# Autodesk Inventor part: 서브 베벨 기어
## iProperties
Created: 2014-10
Part Number: 서브 베벨 기어
Material: Steel, Mild
Document SubType Name: Modeling
Designer: KYOUNG IL JANG
Categories: <?xml version="1.0" encoding="UTF-16"?> <MemberInstance><Categories><FamilyTemplate><FamilyTemplateParameter ValueType="xs:double" Id="1" ObjectReferenceKey="da
Mass: 134.866 g
Surface Area: 63.6518 cm^2
Volume: 17.1585 cm^3
Density: 7.86 g/cm^3
CustomPartVersion: 1
Author: SeoGD™ [www.esajin.kr]
Revision Number: 1
